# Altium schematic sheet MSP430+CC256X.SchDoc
size A3
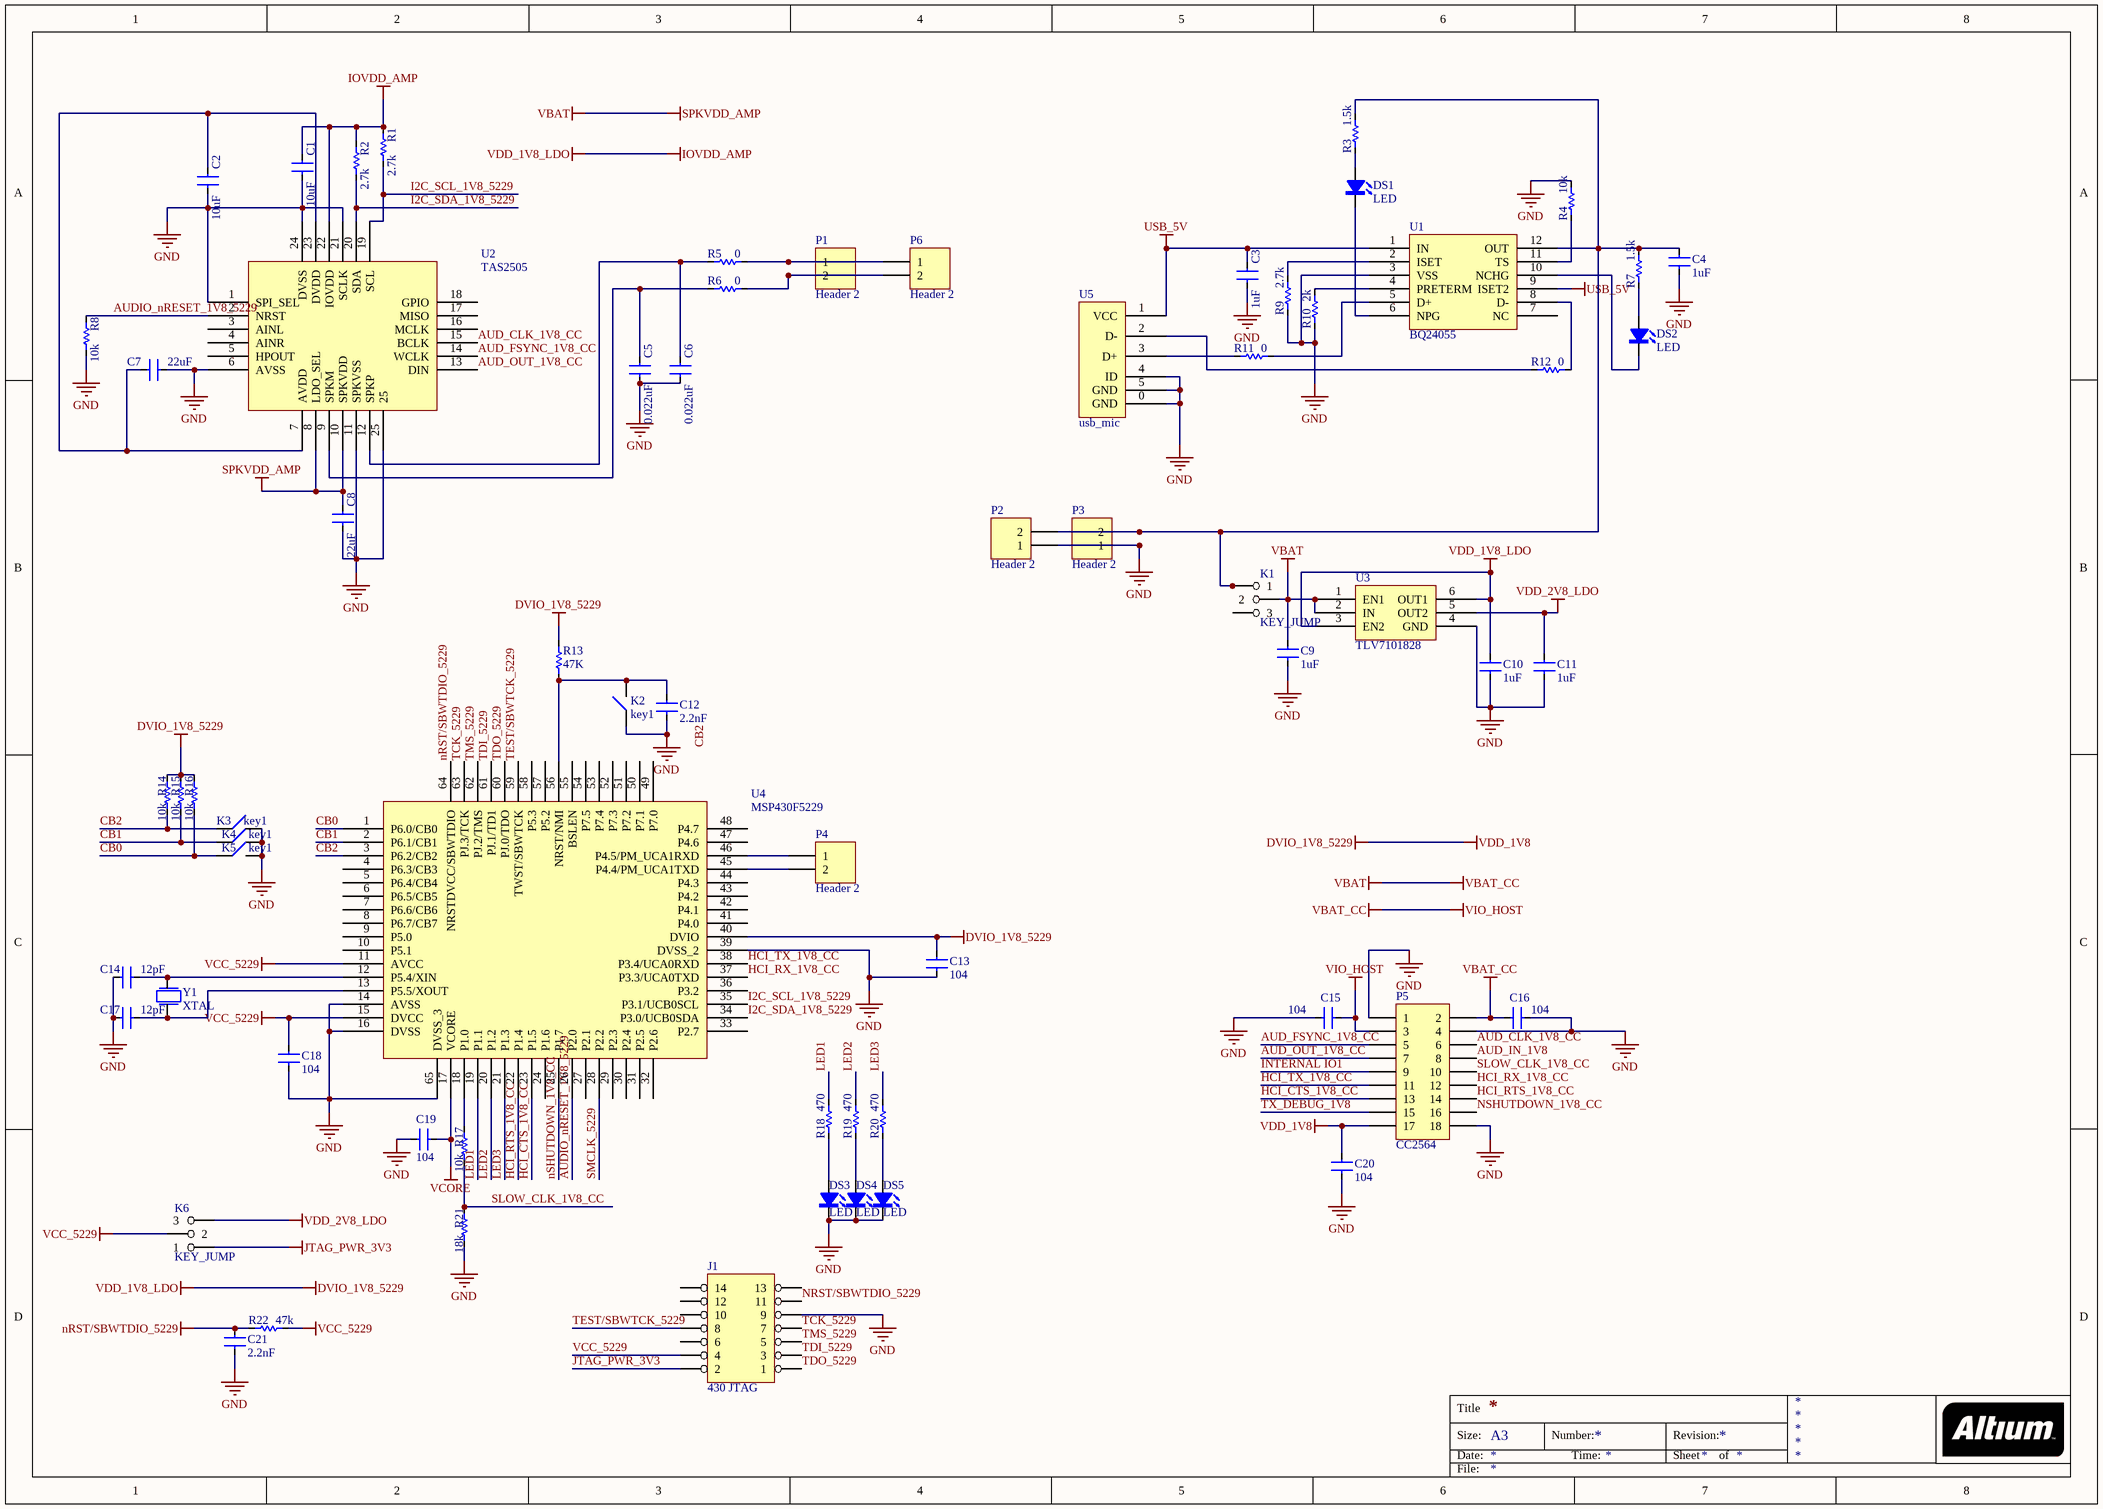
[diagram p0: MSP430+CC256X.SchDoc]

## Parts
C1  10uF  [0603AC]
C2  10uF  [0603AC]
C3  1uF  [0603AC]
C4  1uF  [0603AC]
C5  0.022uF  [0603AC]
C6  0.022uF  [0603AC]
C7  22uF  [0603AC]
C8  22uF  [0603AC]
C9  1uF  [0603AC]
C10  1uF  [0603AC]
C11  1uF  [0603AC]
C12  2.2nF  [0603AC]
C13  104  [0603AC]
C14  12pF  [0603AC]
C15  104  [0603AC]
C16  104  [0603AC]
C17  12pF  [0603AC]
C18  104  [0603AC]
C19  104  [0603AC]
C20  104  [0603AC]
C21  2.2nF  [0603AC]
DS1  LED  [0603AR]
DS2  LED  [0603AR]
DS3  LED  [0603AR]
DS4  LED  [0603AR]
DS5  LED  [0603AR]
J1  430 JTAG  [JTAG]
K1  KEY_JUMP  [拨动2.5mm]
K2  key1  [微动开关-2]
K3  key1  [微动开关-2]
K4  key1  [微动开关-2]
K5  key1  [微动开关-2]
K6  KEY_JUMP  [拨动2.5mm]
P1  Header 2  [HDR1X2]
P2  Header 2  [接线端子-RM5-2]
P3  Header 2  [HDR1X2]
P4  Header 2  [HDR1X2]
P5  CC2564  [DB-2X9]
P6  Header 2  [接线端子-RM5-2]
R1  2.7k  [0603AR]
R2  2.7k  [0603AR]
R3  1.5k  [0603AR]
R4  10k  [0603AR]
R5  0  [0603AR]
R6  0  [0603AR]
R7  1.5k  [0603AR]
R8  10k  [0603AR]
R9  2.7k  [0603AR]
R10  2k  [0603AR]
R11  0  [0603AR]
R12  0  [0603AR]
R13  47K  [0603AR]
R14  10k  [0603AR]
R15  10k  [0603AR]
R16  10k  [0603AR]
R17  10k  [0603AR]
R18  470  [0603AR]
R19  470  [0603AR]
R20  470  [0603AR]
R21  18k  [0603AR]
R22  47k  [0603AR]
U1  BQ24055  [BQ24055]
U2  TAS2505  [QFN24]
U3  TLV7101828  [TLV7101828]
U4  MSP430F5229  [QFN64]
U5  usb_mic  [USB-MICRO]
Y1  XTAL  [XTAL-32768]

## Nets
DVIO_1V8_5229: C1.1 C10.1 C13.1 C20.1 P5.17 R1.2 R2.2 R13.2 R14.2 R15.2 R16.2 U2.22(IOVDD) U3.3(EN2) U3.6(OUT1) U4.40(DVIO)  [also labelled IOVDD_AMP, VDD_1V8, VDD_1V8_LDO]
GND: C1.2 C2.2 C3.2 C4.2 C5.2 C6.2 C7.1 C8.2 C9.2 C10.2 C11.2 C12.2 C13.2 C14.2 C15.2 C16.1 C17.2 C18.2 C19.2 C20.2 C21.2 DS3.2 DS4.2 DS5.2 J1.9 K2.1 K3.2 K4.2 K5.2 P2.1 P3.1 P5.1 P5.4 P5.18 R4.2 R8.1 R9.1 R10.1 R21.1 U1.3(VSS) U2.1(SPI_SEL) U2.6(AVSS) U2.11(SPKVSS) U2.21(SCLK) U2.24(DVSS) U2.25 U3.4(GND) U4.14(AVSS) U4.16(DVSS) U4.39(DVSS_2) U4.65(DVSS_3) U5.0(GND) U5.4(ID) U5.5(GND)
JTAG_PWR_3V3: J1.2 K6.1
nRST/SBWTDIO_5229: C21.1 J1.11 R22.1 U4.64(NRSTDVCC/SBWTDIO)
SPKVDD_AMP: C8.1 C9.1 C15.1 C16.2 K1.2 P5.2 P5.3 U2.8(LDO_SEL) U2.10(SPKVDD) U3.1(EN1) U3.2(IN)  [also labelled VBAT, VBAT_CC, VIO_HOST]
USB_5V: C3.1 U1.1(IN) U1.9(ISET2) U5.1(VCC)
VCC_5229: C18.1 J1.4 K6.2 R22.2 U4.11(AVCC) U4.15(DVCC)
VCORE: C19.1 U4.17(VCORE)
VDD_2V8_LDO: C11.1 K6.3 U3.5(OUT2)
AUD_CLK_1V8_CC: P5.6 U2.15(BCLK)
AUD_FSYNC_1V8_CC: P5.5 U2.14(WCLK)
AUD_IN_1V8: P5.8
AUD_OUT_1V8_CC: P5.7 U2.13(DIN)
AUDIO_nRESET_1V8_5229: R8.2 U2.2(NRST) U4.26(P2.0)
CB0: K5.1 R16.1 U4.1(P6.0/CB0)
CB1: K4.1 R15.1 U4.2(P6.1/CB1)
CB2: K3.1 R14.1 U4.3(P6.2/CB2)
HCI_CTS_1V8_CC: P5.13 U4.23(P1.5)
HCI_RTS_1V8_CC: P5.14 U4.22(P1.4)
HCI_RX_1V8_CC: P5.12 U4.37(P3.3/UCA0TXD)
HCI_TX_1V8_CC: P5.11 U4.38(P3.4/UCA0RXD)
I2C_SCL_1V8_5229: R1.1 U2.19(SCL) U4.35(P3.1/UCB0SCL)
I2C_SDA_1V8_5229: R2.1 U2.20(SDA) U4.34(P3.0/UCB0SDA)
INTERNAL IO1: P5.9
LED1: R18.2 U4.19(P1.1)
LED2: R19.2 U4.20(P1.2)
LED3: R20.2 U4.21(P1.3)
nSHUTDOWN_1V8_CC: P5.16 U4.25(P1.7)
SLOW_CLK_1V8_CC: P5.10 R17.1 R21.2
SMCLK_5229: U4.28(P2.2)
TCK_5229: J1.7 U4.63(PJ.3/TCK)
TDI_5229: J1.3 U4.61(PJ.1/TD1)
TDO_5229: J1.1 U4.60(PJ.0/TDO)
TEST/SBWTCK_5229: J1.8 U4.59(TWST/SBWTCK)
TMS_5229: J1.5 U4.62(PJ.2/TMS)
TX_DEBUG_1V8: P5.15
NetC2_1: C2.1 C7.2 U2.7(AVDD) U2.23(DVDD)
NetC4_1: C4.1 K1.1 P2.2 P3.2 R3.2 R7.2 U1.12(OUT)
NetC5_1: C5.1 R6.2 U2.9(SPKM)
NetC6_1: C6.1 R5.2 U2.12(SPKP)
NetC12_1: C12.1 K2.2 R13.1 U4.56(NRST/NMI)
NetC14_1: C14.1 U4.12(P5.4/XIN) Y1.2
NetC17_1: C17.1 U4.13(P5.5/XOUT) Y1.1
NetDS1_1: DS1.1 R3.1
NetDS1_2: DS1.2 U1.6(NPG)
NetDS2_1: DS2.1 R7.1
NetDS2_2: DS2.2 U1.10(NCHG)
NetDS3_1: DS3.1 R18.1
NetDS4_1: DS4.1 R19.1
NetDS5_1: DS5.1 R20.1
NetP1_1: P1.1 P6.1 R5.1
NetP1_2: P1.2 P6.2 R6.1
NetP4_1: P4.1 U4.46(P4.5/PM_UCA1RXD)
NetP4_2: P4.2 U4.45(P4.4/PM_UCA1TXD)
NetR4_1: R4.1 U1.11(TS)
NetR9_2: R9.2 U1.2(ISET)
NetR10_2: R10.2 U1.4(PRETERM)
NetR11_1: R11.1 U1.5(D+)
NetR11_2: R11.2 U5.3(D+)
NetR12_1: R12.1 U1.8(D-)
NetR12_2: R12.2 U5.2(D-)
NetR17_2: R17.2 U4.18(P1.0)

Not connected (* = marked no-connect by the designer): J1 6 10 12 13 14; K1 3; U1 7(NC); U2 3(AINL) 4(AINR) 5(HPOUT) 16(MCLK) 17(MISO) 18(GPIO); U4 4(P6.3/CB3) 5(P6.4/CB4) 6(P6.5/CB5) 7(P6.6/CB6) 8(P6.7/CB7) 9(P5.0) 10(P5.1) 24(P1.6) 27(P2.1) 29(P2.3) 30(P2.4) 31(P2.5) 32(P2.6) 33(P2.7) 36(P3.2) 41(P4.0) 42(P4.1) 43(P4.2) 44(P4.3) 47(P4.6) 48(P4.7) 49(P7.0) 50(P7.1) 51(P7.2) 52(P7.3) 53(P7.4) 54(P7.5) 55(BSLEN) 57(P5.2) 58(P5.3)

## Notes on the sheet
- Labels drawn without touching a wire or pin: CB2

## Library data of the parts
C1-C21 = CAP: SMD-CAP
P1-P4 P6 = Header 2: Header, 2-Pin
P5 = Header 9X2: Header, 9-Pin, Dual row
R1-R22 = RES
